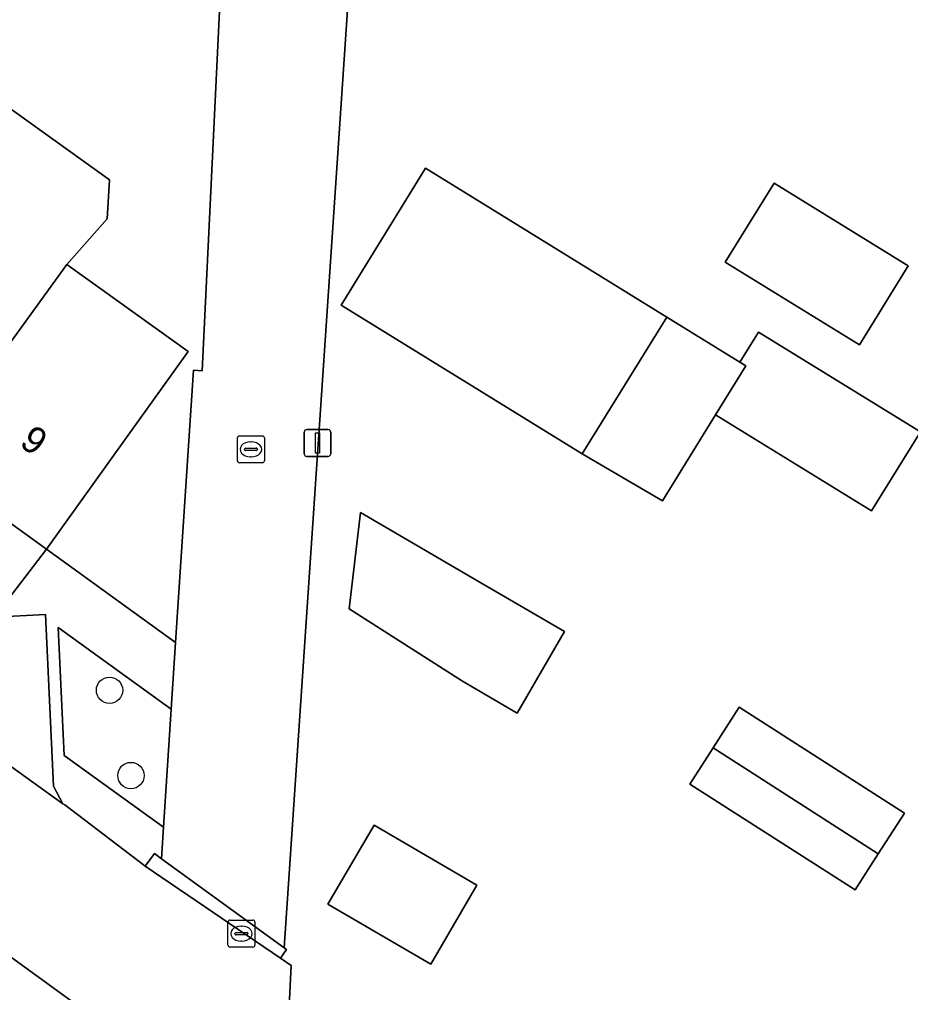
# Model space of a CAD drawing. Extents: x 160102 to 160934, y 382045 to 382923.
# Drawn here: x 160503.2 to 160536.3, y 382456.15 to 382492.3 of the extents above; entities that cross this region are included whole.
import ezdxf

# ---------------------------------------------------------------- set-up
doc = ezdxf.new("R2010")
doc.units = 0
for name, color, linetype in [('IMGEO_Boom', 7, 'Continuous'), ('IMGEO_Erf', 7, 'Continuous'), ('IMGEO_Groenvoorziening', 7, 'Continuous'), ('IMGEO_Kolk', 7, 'Continuous'), ('IMGEO_Lichtmast', 7, 'Continuous'), ('IMGEO_Pand', 7, 'Continuous'), ('IMGEO_Pand_nummerreeks', 7, 'Continuous'), ('IMGEO_Parkeervlak_open', 7, 'Continuous'), ('IMGEO_Rijbaan_lokaal_open', 7, 'Continuous'), ('IMGEO_Voetpad_open', 7, 'Continuous')]:
    doc.layers.add(name, color=color, linetype=linetype)

msp = doc.modelspace()

# ---------------------------------------------------------------- linework, layer by layer
at = {"layer": 'IMGEO_Boom'}
for centre in [(160506.547, 382467.382), (160507.343, 382464.215)]:
    msp.add_circle(centre, 0.489, dxfattribs=at)
at = {"layer": 'IMGEO_Erf'}
for points in [[(160515.877, 382500), (160513.04, 382457.812), (160513.127, 382457.749), (160512.897, 382457.431), (160513.29, 382457.164), (160512.858, 382448.391), (160512.789, 382447.326), (160510.66, 382410.418), (160510.596, 382409.264), (160507.91, 382360.033)], [(160485.427, 382495.063), (160490.171, 382491.653), (160494.999, 382488.182), (160496.03, 382489.598), (160500, 382486.752), (160500.574, 382486.34), (160502.084, 382488.012), (160502.508, 382489.245), (160506.547, 382486.349), (160506.454, 382484.894), (160504.962, 382483.194), (160509.469, 382479.962), (160507.118, 382476.684), (160504.203, 382472.621), (160509, 382469.155), (160509.669, 382479.278), (160509.987, 382479.244), (160510.797, 382495.971)]]:
    msp.add_lwpolyline(points, dxfattribs=at)
for points in [[(160527.244, 382481.249), (160529.966, 382479.57), (160530.656, 382480.689), (160536.666, 382476.981), (160534.855, 382474.045), (160529.062, 382477.619), (160527.092, 382474.425), (160524.108, 382476.167), (160515.152, 382481.693), (160518.287, 382486.775)], [(160536.211, 382483.148), (160534.403, 382480.217), (160529.421, 382483.291), (160531.229, 382486.222)], [(160520.195, 382471.464), (160523.453, 382469.565), (160521.689, 382466.538), (160519.659, 382467.721), (160515.444, 382470.411), (160515.875, 382473.982)], [(160528.966, 382465.243), (160529.937, 382466.758), (160536.077, 382462.821), (160535.102, 382461.301), (160534.245, 382459.964), (160528.105, 382463.901)], [(160516.374, 382462.369), (160520.19, 382460.144), (160518.479, 382457.208), (160514.662, 382459.432)]]:
    msp.add_lwpolyline(points, close=True, dxfattribs=at)
at = {"layer": 'IMGEO_Groenvoorziening'}
msp.add_lwpolyline([(160508.547, 382462.296), (160508.837, 382466.683), (160504.64, 382469.716), (160504.864, 382464.957)], close=True, dxfattribs=at)
at = {"layer": 'IMGEO_Kolk'}
for p, q in [((160511.298, 382475.908), (160511.298, 382476.76)), ((160511.373, 382476.834), (160512.225, 382476.834)), ((160512.299, 382476.76), (160512.299, 382475.908)), ((160511.557, 382476.328), (160511.557, 382476.34)), ((160511.995, 382476.291), (160511.597, 382476.291)), ((160511.6, 382476.377), (160511.998, 382476.377)), ((160511.786, 382476.614), (160511.811, 382476.614)), ((160512.041, 382476.34), (160512.041, 382476.328)), ((160511.809, 382476.054), (160511.784, 382476.054)), ((160512.225, 382475.834), (160511.373, 382475.834)), ((160510.948, 382457.917), (160510.948, 382458.769)), ((160511.023, 382458.843), (160511.875, 382458.843)), ((160511.436, 382458.623), (160511.461, 382458.623)), ((160511.949, 382458.769), (160511.949, 382457.917)), ((160511.207, 382458.337), (160511.207, 382458.349)), ((160511.645, 382458.3), (160511.247, 382458.3)), ((160511.25, 382458.386), (160511.648, 382458.386)), ((160511.691, 382458.349), (160511.691, 382458.337)), ((160511.875, 382457.843), (160511.023, 382457.843)), ((160511.459, 382458.063), (160511.434, 382458.063))]:
    msp.add_line(p, q, dxfattribs=at)
for points in [[(160511.298, 382475.908), (160511.298, 382476.76)], [(160511.373, 382476.834), (160512.225, 382476.834)], [(160512.299, 382476.76), (160512.299, 382475.908)], [(160512.225, 382475.834), (160511.373, 382475.834)], [(160510.948, 382457.917), (160510.948, 382458.769)], [(160511.023, 382458.843), (160511.875, 382458.843)], [(160511.949, 382458.769), (160511.949, 382457.917)], [(160511.875, 382457.843), (160511.023, 382457.843)]]:
    msp.add_lwpolyline(points, dxfattribs=at)
for centre, radius, start, end in [((160511.375, 382476.758), 0.0765, 91.552, 178.448), ((160511.375, 382476.758), 0.0765, 91.552, 178.448), ((160512.223, 382476.758), 0.0765, 1.552, 88.448), ((160512.223, 382476.758), 0.0765, 1.552, 88.448), ((160511.597, 382476.337), 0.0403, 85.8775, 175.7526), ((160511.594, 382476.327), 0.0366, 178.938, 274.7102), ((160511.998, 382476.334), 0.043, 264.8664, 352.4533), ((160512.002, 382476.339), 0.0386, 1.7309, 96.639), ((160511.375, 382475.91), 0.0765, 181.552, 268.448), ((160511.375, 382475.91), 0.0765, 181.552, 268.448), ((160512.223, 382475.91), 0.0765, 271.552, 358.448), ((160512.223, 382475.91), 0.0765, 271.552, 358.448), ((160511.025, 382458.767), 0.0765, 91.552, 178.448), ((160511.025, 382458.767), 0.0765, 91.552, 178.448), ((160511.873, 382458.767), 0.0765, 1.552, 88.448), ((160511.873, 382458.767), 0.0765, 1.552, 88.448), ((160511.247, 382458.346), 0.0403, 85.8775, 175.7526), ((160511.244, 382458.336), 0.0366, 178.938, 274.7102), ((160511.648, 382458.343), 0.043, 264.8664, 352.4533), ((160511.652, 382458.348), 0.0386, 1.7309, 96.639), ((160511.025, 382457.919), 0.0765, 181.552, 268.448), ((160511.025, 382457.919), 0.0765, 181.552, 268.448), ((160511.873, 382457.919), 0.0765, 271.552, 358.448), ((160511.873, 382457.919), 0.0765, 271.552, 358.448)]:
    msp.add_arc(centre, radius, start, end, dxfattribs=at)
for centre, major_axis, ratio, start_param, end_param in [((160511.785, 382476.334), (-0.387, 0.002), 0.722429, 4.712389, 7.853982), ((160511.81, 382476.334), (-0.39, 0.002), 0.717154, 1.570796, 4.712389), ((160511.435, 382458.343), (-0.387, 0.002), 0.722429, 4.712389, 7.853982), ((160511.46, 382458.343), (-0.39, 0.002), 0.717154, 1.570796, 4.712389)]:
    msp.add_ellipse(centre, major_axis=major_axis, ratio=ratio, start_param=start_param, end_param=end_param, dxfattribs=at)
at = {"layer": 'IMGEO_Lichtmast'}
for p, q in [((160513.876, 382477.072), (160514.666, 382477.072)), ((160514.666, 382477.072), (160513.876, 382477.072)), ((160513.776, 382476.172), (160513.776, 382476.972)), ((160513.776, 382476.972), (160513.776, 382476.172)), ((160514.766, 382476.972), (160514.766, 382476.172)), ((160514.766, 382476.172), (160514.766, 382476.972)), ((160514.666, 382476.072), (160513.876, 382476.072)), ((160513.876, 382476.072), (160514.666, 382476.072))]:
    msp.add_line(p, q, dxfattribs=at)
msp.add_lwpolyline([(160514.196, 382476.947), (160514.346, 382476.947), (160514.346, 382476.197), (160514.196, 382476.197), (160514.196, 382476.947)], dxfattribs=at)
for centre, start, end in [((160513.876, 382476.972), 90, 180), ((160513.876, 382476.972), 90, 180), ((160514.666, 382476.972), 0, 90), ((160514.666, 382476.972), 360, 90), ((160513.876, 382476.172), 180, 270), ((160513.876, 382476.172), 180, 270), ((160514.666, 382476.172), 270, 0), ((160514.666, 382476.172), 270, 0)]:
    msp.add_arc(centre, 0.1, start, end, dxfattribs=at)
at = {"layer": 'IMGEO_Pand'}
for points in [[(160495.294, 382479.056), (160499.67, 382475.895), (160500, 382476.35), (160504.962, 382483.194), (160506.454, 382484.894), (160506.547, 382486.349), (160502.508, 382489.245), (160502.084, 382488.012), (160500.574, 382486.34), (160500, 382485.549)], [(160515.152, 382481.693), (160524.108, 382476.167), (160527.244, 382481.249), (160518.287, 382486.775)], [(160529.421, 382483.291), (160534.403, 382480.217), (160536.211, 382483.148), (160531.229, 382486.222)], [(160504.962, 382483.194), (160500, 382476.35), (160499.67, 382475.895), (160500, 382475.657), (160504.203, 382472.621), (160507.118, 382476.684), (160509.469, 382479.962)], [(160529.966, 382479.57), (160527.244, 382481.249), (160524.108, 382476.167), (160527.092, 382474.425), (160529.062, 382477.619), (160530.183, 382479.436)], [(160529.966, 382479.57), (160530.183, 382479.436), (160529.062, 382477.619), (160534.855, 382474.045), (160536.666, 382476.981), (160530.656, 382480.689)], [(160520.195, 382471.464), (160515.875, 382473.982), (160515.444, 382470.411), (160519.659, 382467.721), (160521.689, 382466.538), (160523.453, 382469.565)], [(160528.966, 382465.243), (160535.102, 382461.301), (160536.077, 382462.821), (160529.937, 382466.758)], [(160528.966, 382465.243), (160528.105, 382463.901), (160534.245, 382459.964), (160535.102, 382461.301)], [(160514.662, 382459.432), (160518.479, 382457.208), (160520.19, 382460.144), (160516.374, 382462.369)]]:
    msp.add_lwpolyline(points, close=True, dxfattribs=at)
at = {"layer": 'IMGEO_Parkeervlak_open'}
msp.add_lwpolyline([(160489.33, 382474.327), (160504.818, 382463.168), (160504.466, 382463.82), (160504.166, 382470.194), (160502.265, 382470.103), (160501.85, 382470.083), (160501.742, 382471.931), (160500, 382471.863), (160499.45, 382471.842), (160499.351, 382473.682), (160497.051, 382473.57), (160496.963, 382475.404), (160494.605, 382475.324), (160494.522, 382477.167), (160492.215, 382477.051), (160492.118, 382478.901), (160489.929, 382478.847), (160490.092, 382475.241)], dxfattribs=at)
at = {"layer": 'IMGEO_Rijbaan_lokaal_open'}
msp.add_lwpolyline([(160508.547, 382462.296), (160508.479, 382461.121), (160513.04, 382457.812), (160515.877, 382500), (160517.912, 382530.251), (160519.19, 382547.212), (160516.275, 382549.725), (160515.795, 382546.76), (160514.431, 382538.585), (160514.141, 382536.828), (160513.795, 382534.731), (160512.903, 382527.769), (160512.81, 382526.575), (160512.45, 382521.097), (160511.062, 382500), (160510.875, 382497.164), (160510.797, 382495.971), (160509.987, 382479.244), (160509.669, 382479.278), (160509, 382469.155), (160508.837, 382466.683)], close=True, dxfattribs=at)
for points in [[(160457.122, 382490.711), (160457.364, 382490.549), (160507.529, 382454.102)], [(160508.827, 382450.731), (160508.68, 382448.66), (160512.858, 382448.391), (160513.29, 382457.164), (160512.897, 382457.431), (160507.875, 382460.848), (160507.807, 382460.895), (160504.882, 382463.122), (160504.818, 382463.168), (160489.33, 382474.327)]]:
    msp.add_lwpolyline(points, dxfattribs=at)
at = {"layer": 'IMGEO_Voetpad_open'}
for points in [[(160507.529, 382454.102), (160457.364, 382490.549)], [(160490.092, 382475.241), (160489.929, 382478.847), (160492.118, 382478.901), (160492.215, 382477.051), (160494.522, 382477.167), (160494.605, 382475.324), (160496.963, 382475.404), (160497.051, 382473.57), (160499.351, 382473.682), (160499.45, 382471.842), (160500, 382471.863), (160501.742, 382471.931), (160501.85, 382470.083), (160502.265, 382470.103), (160504.203, 382472.621), (160500, 382475.657), (160499.67, 382475.895), (160495.294, 382479.056), (160490.747, 382482.341), (160487.6, 382477.986), (160478.067, 382484.825), (160476.971, 382485.611), (160476.429, 382483.621), (160489.33, 382474.327)]]:
    msp.add_lwpolyline(points, dxfattribs=at)
for points in [[(160504.818, 382463.168), (160504.882, 382463.122), (160507.807, 382460.895), (160507.875, 382460.848), (160508.213, 382461.314), (160508.479, 382461.121), (160508.547, 382462.296), (160504.864, 382464.957), (160504.64, 382469.716), (160508.837, 382466.683), (160509, 382469.155), (160504.203, 382472.621), (160502.265, 382470.103), (160504.166, 382470.194), (160504.466, 382463.82)], [(160512.897, 382457.431), (160513.127, 382457.749), (160513.04, 382457.812), (160508.479, 382461.121), (160508.213, 382461.314), (160507.875, 382460.848)]]:
    msp.add_lwpolyline(points, close=True, dxfattribs=at)

# ---------------------------------------------------------------- texts
at = {"layer": 'IMGEO_Pand_nummerreeks'}
msp.add_text('9', height=1, rotation=324.1566, dxfattribs=at).set_placement((160503.157, 382476.485))

doc.saveas('drawing.dxf')
